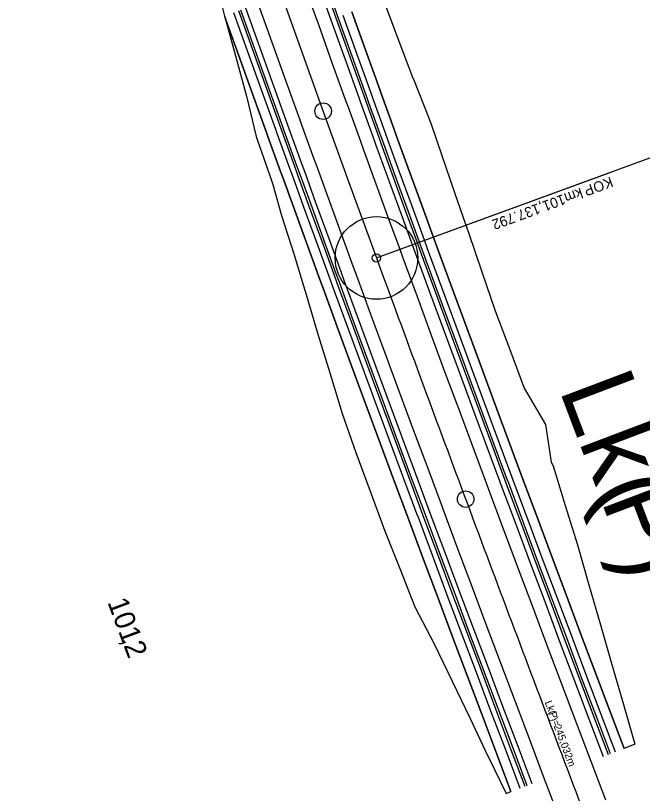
# Model space of a CAD drawing. Extents: x -678487 to -674601, y -1104811 to -1093295.
# Drawn here: x -677039.7 to -676888, y -1098001.8 to -1097813.6 of the extents above; entities that cross this region are included whole.
import ezdxf

# ---------------------------------------------------------------- set-up
doc = ezdxf.new("R2010")
doc.units = 0
for name, color, linetype in [('SOxxxxxx_Koleje_hlavní_body_Popis', 7, 'Continuous'), ('SOxxxxxx_Koleje_hlavní_body_Popis10', 7, 'Continuous'), ('SOxxxxxx_Koleje_param další_Popis', 7, 'Continuous'), ('SOxxxxxx_Koleje_param další_Popis10', 7, 'Continuous'), ('SOxxxxxx_Osa_bod_P', 7, 'Continuous'), ('SOxxxxxx_Staničení_Popis', 7, 'Continuous'), ('SOxxxxxx_ŽSp_hrana', 7, 'Continuous'), ('SOxxxxxx_ŽSp_odvodnění', 7, 'Continuous'), ('SOxxxxxx_ŽSp_zářez_hrana', 7, 'Continuous'), ('SOxxxxxx_ŽSp_zářez_plocha', 7, 'Continuous')]:
    doc.layers.add(name, color=color, linetype=linetype)

msp = doc.modelspace()

# ---------------------------------------------------------------- linework, layer by layer
at = {"layer": 'SOxxxxxx_Koleje_hlavní_body_Popis'}
for q in [(-676896.01, -1097851.63), (-676952.35, -1097872.26)]:
    msp.add_line((-676952.35, -1097872.26), q, dxfattribs=at)
msp.add_circle((-676952.35, -1097872.26), 1, dxfattribs=at)
at = {"layer": 'SOxxxxxx_Koleje_hlavní_body_Popis10'}
for q in [(-676388.94, -1097665.94), (-676952.35, -1097872.26)]:
    msp.add_line((-676952.35, -1097872.26), q, dxfattribs=at)
msp.add_circle((-676952.35, -1097872.26), 10, dxfattribs=at)
at = {"layer": 'SOxxxxxx_Osa_bod_P'}
msp.add_arc((-668968.6, -1094948.57), 8502.25, 183.991255, 200.113006, dxfattribs=at)
msp.add_open_spline([(-676952.35, -1097872.26), (-676945.32, -1097891.44), (-676931.16, -1097929.74), (-676909.55, -1097987.06), (-676887.79, -1098044.32), (-676873.18, -1098082.46), (-676865.88, -1098101.53)], degree=3, dxfattribs=at)
at = {"layer": 'SOxxxxxx_Staničení_Popis'}
for p, q in [((-676965.26, -1097836.75), (-676965.26, -1097836.75)), ((-676930.76, -1097930.61), (-676930.76, -1097930.61))]:
    msp.add_line(p, q, dxfattribs=at)
for centre in [(-676965.26, -1097836.75), (-676930.76, -1097930.61)]:
    msp.add_circle(centre, 2, dxfattribs=at)
at = {"layer": 'SOxxxxxx_ŽSp_hrana'}
for p, q in [((-676969.79, -1097806.37), (-676966.42, -1097815.78)), ((-676981.03, -1097810.64), (-676977.66, -1097820.05)), ((-676966.42, -1097815.78), (-676963.04, -1097825.19)), ((-676977.66, -1097820.05), (-676974.27, -1097829.47)), ((-676963.04, -1097825.19), (-676959.65, -1097834.6)), ((-676974.27, -1097829.47), (-676970.88, -1097838.88)), ((-676959.65, -1097834.6), (-676959.31, -1097835.54)), ((-676959.31, -1097835.54), (-676956.25, -1097844.01)), ((-676970.88, -1097838.88), (-676970.54, -1097839.81)), ((-676970.54, -1097839.81), (-676967.48, -1097848.28)), ((-676956.25, -1097844.01), (-676955.48, -1097846.12)), ((-676955.48, -1097846.12), (-676952.83, -1097853.41)), ((-676967.48, -1097848.28), (-676966.71, -1097850.39)), ((-676966.71, -1097850.39), (-676964.07, -1097857.68)), ((-676952.83, -1097853.41), (-676949.41, -1097862.8)), ((-676964.07, -1097857.68), (-676960.64, -1097867.08)), ((-676949.41, -1097862.8), (-676946.73, -1097870.13)), ((-676960.64, -1097867.08), (-676957.96, -1097874.4)), ((-676946.73, -1097870.13), (-676945.97, -1097872.2)), ((-676945.97, -1097872.2), (-676942.52, -1097881.58)), ((-676957.96, -1097874.4), (-676957.21, -1097876.47)), ((-676957.21, -1097876.47), (-676953.76, -1097885.86)), ((-676942.52, -1097881.58), (-676939.07, -1097890.97)), ((-676953.76, -1097885.86), (-676950.3, -1097895.24)), ((-676939.07, -1097890.97), (-676935.6, -1097900.35)), ((-676950.3, -1097895.24), (-676946.83, -1097904.62)), ((-676935.6, -1097900.35), (-676932.12, -1097909.72)), ((-676946.83, -1097904.62), (-676943.36, -1097914)), ((-676932.12, -1097909.72), (-676928.64, -1097919.1)), ((-676943.36, -1097914), (-676939.87, -1097923.37)), ((-676928.64, -1097919.1), (-676925.47, -1097927.58)), ((-676939.87, -1097923.37), (-676936.71, -1097931.85)), ((-676925.47, -1097927.58), (-676925.14, -1097928.47)), ((-676925.14, -1097928.47), (-676921.64, -1097937.83)), ((-676936.71, -1097931.85), (-676936.38, -1097932.74)), ((-676936.38, -1097932.74), (-676932.87, -1097942.11)), ((-676921.64, -1097937.83), (-676918.13, -1097947.2)), ((-676932.87, -1097942.11), (-676929.36, -1097951.47)), ((-676918.13, -1097947.2), (-676914.61, -1097956.56)), ((-676929.36, -1097951.47), (-676925.85, -1097960.83)), ((-676914.61, -1097956.56), (-676911.09, -1097965.92)), ((-676925.85, -1097960.83), (-676922.32, -1097970.19)), ((-676911.09, -1097965.92), (-676907.56, -1097975.27)), ((-676922.32, -1097970.19), (-676918.79, -1097979.55)), ((-676907.56, -1097975.27), (-676903.91, -1097984.91)), ((-676918.79, -1097979.55), (-676915.14, -1097989.19)), ((-676903.91, -1097984.91), (-676900.48, -1097993.98)), ((-676915.14, -1097989.19), (-676911.71, -1097998.25)), ((-676900.48, -1097993.98), (-676896.93, -1098003.33)), ((-676911.71, -1097998.25), (-676908.16, -1098007.6))]:
    msp.add_line(p, q, dxfattribs=at)
at = {"layer": 'SOxxxxxx_ŽSp_odvodnění'}
for p, q in [((-676965.58, -1097804.77), (-676962.22, -1097814.18)), ((-676965.07, -1097804.57), (-676961.7, -1097813.99)), ((-676985.75, -1097812.43), (-676982.38, -1097821.85)), ((-676985.23, -1097812.24), (-676981.86, -1097821.65)), ((-676962.22, -1097814.18), (-676958.83, -1097823.59)), ((-676961.7, -1097813.99), (-676958.32, -1097823.4)), ((-676982.38, -1097821.85), (-676978.99, -1097831.26)), ((-676981.86, -1097821.65), (-676978.48, -1097831.07)), ((-676958.83, -1097823.59), (-676955.44, -1097833)), ((-676958.32, -1097823.4), (-676954.93, -1097832.81)), ((-676978.99, -1097831.26), (-676975.6, -1097840.67)), ((-676978.48, -1097831.07), (-676975.09, -1097840.48)), ((-676955.44, -1097833), (-676955.1, -1097833.94)), ((-676955.1, -1097833.94), (-676952.04, -1097842.41)), ((-676954.93, -1097832.81), (-676954.59, -1097833.74)), ((-676954.59, -1097833.74), (-676951.53, -1097842.21)), ((-676975.6, -1097840.67), (-676975.26, -1097841.61)), ((-676975.26, -1097841.61), (-676972.2, -1097850.08)), ((-676975.09, -1097840.48), (-676974.75, -1097841.41)), ((-676974.75, -1097841.41), (-676971.69, -1097849.88)), ((-676952.04, -1097842.41), (-676951.27, -1097844.52)), ((-676951.53, -1097842.21), (-676950.76, -1097844.32)), ((-676951.27, -1097844.52), (-676948.63, -1097851.81)), ((-676950.76, -1097844.32), (-676948.11, -1097851.61)), ((-676972.2, -1097850.08), (-676971.43, -1097852.19)), ((-676971.69, -1097849.88), (-676970.92, -1097851.99)), ((-676971.43, -1097852.19), (-676968.79, -1097859.48)), ((-676970.92, -1097851.99), (-676968.27, -1097859.28)), ((-676948.63, -1097851.81), (-676945.2, -1097861.2)), ((-676948.11, -1097851.61), (-676944.69, -1097861.01)), ((-676968.79, -1097859.48), (-676965.36, -1097868.87)), ((-676968.27, -1097859.28), (-676964.85, -1097868.68)), ((-676945.2, -1097861.2), (-676942.52, -1097868.53)), ((-676944.69, -1097861.01), (-676942.01, -1097868.33)), ((-676965.36, -1097868.87), (-676962.68, -1097876.2)), ((-676964.85, -1097868.68), (-676962.17, -1097876)), ((-676942.52, -1097868.53), (-676941.77, -1097870.59)), ((-676942.01, -1097868.33), (-676941.25, -1097870.4)), ((-676941.77, -1097870.59), (-676938.32, -1097879.98)), ((-676941.25, -1097870.4), (-676937.8, -1097879.79)), ((-676962.68, -1097876.2), (-676961.92, -1097878.27)), ((-676962.17, -1097876), (-676961.41, -1097878.07)), ((-676961.92, -1097878.27), (-676958.48, -1097887.65)), ((-676961.41, -1097878.07), (-676957.96, -1097887.46)), ((-676938.32, -1097879.98), (-676934.86, -1097889.37)), ((-676937.8, -1097879.79), (-676934.35, -1097889.17)), ((-676958.48, -1097887.65), (-676955.02, -1097897.04)), ((-676957.96, -1097887.46), (-676954.51, -1097896.84)), ((-676934.86, -1097889.37), (-676931.39, -1097898.75)), ((-676934.35, -1097889.17), (-676930.88, -1097898.55)), ((-676955.02, -1097897.04), (-676951.55, -1097906.42)), ((-676954.51, -1097896.84), (-676951.04, -1097906.22)), ((-676931.39, -1097898.75), (-676927.92, -1097908.12)), ((-676930.88, -1097898.55), (-676927.4, -1097907.93)), ((-676951.55, -1097906.42), (-676948.08, -1097915.79)), ((-676951.04, -1097906.22), (-676947.56, -1097915.6)), ((-676927.92, -1097908.12), (-676924.43, -1097917.5)), ((-676927.4, -1097907.93), (-676923.92, -1097917.3)), ((-676948.08, -1097915.79), (-676944.59, -1097925.17)), ((-676947.56, -1097915.6), (-676944.08, -1097924.97)), ((-676924.43, -1097917.5), (-676921.27, -1097925.98)), ((-676923.92, -1097917.3), (-676920.75, -1097925.78)), ((-676944.59, -1097925.17), (-676941.43, -1097933.65)), ((-676944.08, -1097924.97), (-676940.91, -1097933.45)), ((-676921.27, -1097925.98), (-676920.94, -1097926.87)), ((-676920.75, -1097925.78), (-676920.42, -1097926.67)), ((-676920.94, -1097926.87), (-676917.43, -1097936.23)), ((-676920.42, -1097926.67), (-676916.92, -1097936.04)), ((-676941.43, -1097933.65), (-676941.1, -1097934.54)), ((-676940.91, -1097933.45), (-676940.58, -1097934.34)), ((-676941.1, -1097934.54), (-676937.59, -1097943.9)), ((-676940.58, -1097934.34), (-676937.08, -1097943.71)), ((-676917.43, -1097936.23), (-676913.92, -1097945.6)), ((-676916.92, -1097936.04), (-676913.41, -1097945.4)), ((-676937.59, -1097943.9), (-676934.08, -1097953.27)), ((-676937.08, -1097943.71), (-676933.57, -1097953.07)), ((-676913.92, -1097945.6), (-676910.41, -1097954.96)), ((-676913.41, -1097945.4), (-676909.89, -1097954.76)), ((-676934.08, -1097953.27), (-676930.57, -1097962.63)), ((-676933.57, -1097953.07), (-676930.05, -1097962.43)), ((-676910.41, -1097954.96), (-676906.88, -1097964.32)), ((-676909.89, -1097954.76), (-676906.37, -1097964.12)), ((-676930.57, -1097962.63), (-676927.04, -1097971.99)), ((-676930.05, -1097962.43), (-676926.53, -1097971.79)), ((-676906.88, -1097964.32), (-676903.35, -1097973.67)), ((-676906.37, -1097964.12), (-676902.84, -1097973.48)), ((-676927.04, -1097971.99), (-676923.51, -1097981.34)), ((-676926.53, -1097971.79), (-676923, -1097981.15)), ((-676902.84, -1097973.48), (-676899.19, -1097983.12)), ((-676903.35, -1097973.67), (-676899.7, -1097983.31)), ((-676923.51, -1097981.34), (-676919.86, -1097990.99)), ((-676923, -1097981.15), (-676919.35, -1097990.79)), ((-676899.7, -1097983.31), (-676896.27, -1097992.38)), ((-676899.19, -1097983.12), (-676895.76, -1097992.18)), ((-676919.86, -1097990.99), (-676916.43, -1098000.05)), ((-676919.35, -1097990.79), (-676915.92, -1097999.85))]:
    msp.add_line(p, q, dxfattribs=at)
at = {"layer": 'SOxxxxxx_ŽSp_zářez_hrana'}
for p, q in [((-676966.78, -1097805.22), (-676963.41, -1097814.64)), ((-676990.51, -1097808.03), (-676989.16, -1097813.73)), ((-676950.65, -1097809.78), (-676947.18, -1097819.16)), ((-676986.94, -1097812.89), (-676983.57, -1097822.3)), ((-676984.04, -1097811.78), (-676980.67, -1097821.2)), ((-676960.5, -1097813.53), (-676957.12, -1097822.94)), ((-676958.34, -1097812.71), (-676954.96, -1097822.12)), ((-676989.16, -1097813.73), (-676985.74, -1097823.13)), ((-676989.12, -1097813.71), (-676986.46, -1097823.4)), ((-676963.41, -1097814.64), (-676960.03, -1097824.05)), ((-676947.18, -1097819.16), (-676943.61, -1097828.5)), ((-676983.57, -1097822.3), (-676980.19, -1097831.72)), ((-676980.67, -1097821.2), (-676977.28, -1097830.61)), ((-676957.12, -1097822.94), (-676953.73, -1097832.35)), ((-676954.96, -1097822.12), (-676951.56, -1097831.53)), ((-676986.46, -1097823.4), (-676983.83, -1097833.1)), ((-676985.74, -1097823.13), (-676982.36, -1097832.54)), ((-676960.03, -1097824.05), (-676956.64, -1097833.46)), ((-676943.61, -1097828.5), (-676943.24, -1097829.42)), ((-676943.24, -1097829.42), (-676939.88, -1097837.78)), ((-676980.19, -1097831.72), (-676976.8, -1097841.13)), ((-676977.28, -1097830.61), (-676973.89, -1097840.02)), ((-676953.73, -1097832.35), (-676953.39, -1097833.29)), ((-676951.56, -1097831.53), (-676951.23, -1097832.46)), ((-676983.83, -1097833.1), (-676981.51, -1097842.92)), ((-676982.36, -1097832.54), (-676978.97, -1097841.95)), ((-676956.64, -1097833.46), (-676956.3, -1097834.39)), ((-676953.39, -1097833.29), (-676950.33, -1097841.76)), ((-676951.23, -1097832.46), (-676948.16, -1097840.93)), ((-676956.3, -1097834.39), (-676953.24, -1097842.86)), ((-676939.88, -1097837.78), (-676939.1, -1097839.88)), ((-676976.8, -1097841.13), (-676976.46, -1097842.06)), ((-676973.89, -1097840.02), (-676973.55, -1097840.96)), ((-676973.55, -1097840.96), (-676970.49, -1097849.43)), ((-676950.33, -1097841.76), (-676949.56, -1097843.87)), ((-676948.16, -1097840.93), (-676947.4, -1097843.04)), ((-676939.1, -1097839.88), (-676936.61, -1097847.24)), ((-676981.51, -1097842.92), (-676981.14, -1097843.84)), ((-676978.97, -1097841.95), (-676978.63, -1097842.89)), ((-676978.63, -1097842.89), (-676975.56, -1097851.36)), ((-676976.46, -1097842.06), (-676973.4, -1097850.53)), ((-676953.24, -1097842.86), (-676952.47, -1097844.97)), ((-676947.4, -1097843.04), (-676944.75, -1097850.33)), ((-676981.14, -1097843.84), (-676978.16, -1097852.35)), ((-676952.47, -1097844.97), (-676949.82, -1097852.26)), ((-676949.56, -1097843.87), (-676946.92, -1097851.16)), ((-676936.61, -1097847.24), (-676933.4, -1097856.71)), ((-676973.4, -1097850.53), (-676972.63, -1097852.65)), ((-676970.49, -1097849.43), (-676969.72, -1097851.54)), ((-676946.92, -1097851.16), (-676943.49, -1097860.55)), ((-676944.75, -1097850.33), (-676941.32, -1097859.73)), ((-676978.16, -1097852.35), (-676977.43, -1097854.47)), ((-676975.56, -1097851.36), (-676974.8, -1097853.47)), ((-676972.63, -1097852.65), (-676969.98, -1097859.93)), ((-676969.72, -1097851.54), (-676967.08, -1097858.83)), ((-676949.82, -1097852.26), (-676946.4, -1097861.66)), ((-676977.43, -1097854.47), (-676975.31, -1097861.96)), ((-676974.8, -1097853.47), (-676972.15, -1097860.76)), ((-676933.4, -1097856.71), (-676930.78, -1097864.05)), ((-676969.98, -1097859.93), (-676966.56, -1097869.33)), ((-676967.08, -1097858.83), (-676963.65, -1097868.22)), ((-676943.49, -1097860.55), (-676940.81, -1097867.87)), ((-676941.32, -1097859.73), (-676938.64, -1097867.05)), ((-676975.31, -1097861.96), (-676972.27, -1097871.5)), ((-676972.15, -1097860.76), (-676968.73, -1097870.15)), ((-676946.4, -1097861.66), (-676943.72, -1097868.98)), ((-676930.78, -1097864.05), (-676930.06, -1097866.14)), ((-676930.06, -1097866.14), (-676926.81, -1097875.6)), ((-676940.81, -1097867.87), (-676940.05, -1097869.94)), ((-676938.64, -1097867.05), (-676937.89, -1097869.12)), ((-676966.56, -1097869.33), (-676963.88, -1097876.65)), ((-676963.65, -1097868.22), (-676960.97, -1097875.55)), ((-676943.72, -1097868.98), (-676942.96, -1097871.05)), ((-676940.05, -1097869.94), (-676936.61, -1097879.33)), ((-676937.89, -1097869.12), (-676934.44, -1097878.51)), ((-676972.27, -1097871.5), (-676970, -1097878.98)), ((-676968.73, -1097870.15), (-676966.05, -1097877.48)), ((-676942.96, -1097871.05), (-676939.51, -1097880.44)), ((-676960.97, -1097875.55), (-676960.21, -1097877.62)), ((-676926.81, -1097875.6), (-676923.58, -1097885.07)), ((-676966.05, -1097877.48), (-676965.29, -1097879.55)), ((-676963.88, -1097876.65), (-676963.12, -1097878.72)), ((-676970, -1097878.98), (-676969.37, -1097881.1)), ((-676963.12, -1097878.72), (-676959.67, -1097888.11)), ((-676960.21, -1097877.62), (-676956.77, -1097887)), ((-676936.61, -1097879.33), (-676933.15, -1097888.72)), ((-676934.44, -1097878.51), (-676930.98, -1097887.89)), ((-676969.37, -1097881.1), (-676966.56, -1097890.73)), ((-676965.29, -1097879.55), (-676961.84, -1097888.93)), ((-676939.51, -1097880.44), (-676936.06, -1097889.82)), ((-676923.58, -1097885.07), (-676920.08, -1097894.44)), ((-676959.67, -1097888.11), (-676956.22, -1097897.49)), ((-676956.77, -1097887), (-676953.31, -1097896.39)), ((-676933.15, -1097888.72), (-676929.68, -1097898.1)), ((-676930.98, -1097887.89), (-676927.52, -1097897.27)), ((-676961.84, -1097888.93), (-676958.39, -1097898.32)), ((-676936.06, -1097889.82), (-676932.59, -1097899.2)), ((-676966.56, -1097890.73), (-676963.59, -1097900.3)), ((-676920.08, -1097894.44), (-676916.56, -1097903.8)), ((-676956.22, -1097897.49), (-676952.75, -1097906.87)), ((-676953.31, -1097896.39), (-676949.84, -1097905.77)), ((-676929.68, -1097898.1), (-676926.21, -1097907.47)), ((-676927.52, -1097897.27), (-676924.04, -1097906.65)), ((-676958.39, -1097898.32), (-676954.92, -1097907.7)), ((-676932.59, -1097899.2), (-676929.11, -1097908.58)), ((-676963.59, -1097900.3), (-676960.62, -1097909.87)), ((-676916.56, -1097903.8), (-676911.43, -1097912.55)), ((-676952.75, -1097906.87), (-676949.27, -1097916.25)), ((-676949.84, -1097905.77), (-676946.37, -1097915.14)), ((-676926.21, -1097907.47), (-676922.72, -1097916.85)), ((-676924.04, -1097906.65), (-676920.55, -1097916.02)), ((-676954.92, -1097907.7), (-676951.44, -1097917.08)), ((-676929.11, -1097908.58), (-676925.63, -1097917.95)), ((-676960.62, -1097909.87), (-676957.33, -1097919.31)), ((-676911.43, -1097912.55), (-676910.03, -1097921.7)), ((-676946.37, -1097915.14), (-676942.88, -1097924.52)), ((-676949.27, -1097916.25), (-676945.79, -1097925.62)), ((-676922.72, -1097916.85), (-676919.56, -1097925.33)), ((-676920.55, -1097916.02), (-676917.39, -1097924.5)), ((-676951.44, -1097917.08), (-676947.96, -1097926.45)), ((-676925.63, -1097917.95), (-676922.46, -1097926.43)), ((-676957.33, -1097919.31), (-676953.87, -1097928.7)), ((-676910.03, -1097921.7), (-676909.53, -1097922.53)), ((-676909.53, -1097922.53), (-676906.66, -1097932.13)), ((-676942.88, -1097924.52), (-676939.72, -1097933)), ((-676917.39, -1097924.5), (-676917.06, -1097925.39)), ((-676945.79, -1097925.62), (-676942.62, -1097934.1)), ((-676922.46, -1097926.43), (-676922.13, -1097927.32)), ((-676919.56, -1097925.33), (-676919.23, -1097926.22)), ((-676919.23, -1097926.22), (-676915.72, -1097935.58)), ((-676917.06, -1097925.39), (-676913.56, -1097934.76)), ((-676947.96, -1097926.45), (-676944.79, -1097934.93)), ((-676922.13, -1097927.32), (-676918.63, -1097936.69)), ((-676953.87, -1097928.7), (-676950.74, -1097937.19)), ((-676939.72, -1097933), (-676939.39, -1097933.89)), ((-676939.39, -1097933.89), (-676935.88, -1097943.25)), ((-676906.66, -1097932.13), (-676903.64, -1097941.68)), ((-676944.79, -1097934.93), (-676944.46, -1097935.82)), ((-676944.46, -1097935.82), (-676940.96, -1097945.18)), ((-676942.62, -1097934.1), (-676942.29, -1097934.99)), ((-676942.29, -1097934.99), (-676938.79, -1097944.36)), ((-676915.72, -1097935.58), (-676912.21, -1097944.95)), ((-676913.56, -1097934.76), (-676910.04, -1097944.12)), ((-676950.74, -1097937.19), (-676950.41, -1097938.08)), ((-676918.63, -1097936.69), (-676915.12, -1097946.05)), ((-676950.41, -1097938.08), (-676946.69, -1097947.37)), ((-676935.88, -1097943.25), (-676932.37, -1097952.62)), ((-676903.64, -1097941.68), (-676900.9, -1097951.34)), ((-676940.96, -1097945.18), (-676937.45, -1097954.55)), ((-676938.79, -1097944.36), (-676935.28, -1097953.72)), ((-676912.21, -1097944.95), (-676908.7, -1097954.31)), ((-676910.04, -1097944.12), (-676906.53, -1097953.48)), ((-676915.12, -1097946.05), (-676911.6, -1097955.41)), ((-676946.69, -1097947.37), (-676943.02, -1097956.67)), ((-676932.37, -1097952.62), (-676928.86, -1097961.98)), ((-676900.9, -1097951.34), (-676898.13, -1097960.99)), ((-676937.45, -1097954.55), (-676933.93, -1097963.91)), ((-676935.28, -1097953.72), (-676931.76, -1097963.08)), ((-676908.7, -1097954.31), (-676905.17, -1097963.66)), ((-676906.53, -1097953.48), (-676903, -1097962.84)), ((-676911.6, -1097955.41), (-676908.08, -1097964.77)), ((-676943.02, -1097956.67), (-676938.35, -1097965.59)), ((-676928.86, -1097961.98), (-676925.33, -1097971.34)), ((-676898.13, -1097960.99), (-676895.36, -1097970.63)), ((-676933.93, -1097963.91), (-676930.41, -1097973.27)), ((-676931.76, -1097963.08), (-676928.24, -1097972.44)), ((-676905.17, -1097963.66), (-676901.64, -1097973.02)), ((-676903, -1097962.84), (-676899.47, -1097972.2)), ((-676938.35, -1097965.59), (-676934.04, -1097974.65)), ((-676908.08, -1097964.77), (-676904.55, -1097974.13)), ((-676925.33, -1097971.34), (-676921.8, -1097980.69)), ((-676895.36, -1097970.63), (-676892.58, -1097980.27)), ((-676930.41, -1097973.27), (-676926.87, -1097982.62)), ((-676928.24, -1097972.44), (-676924.71, -1097981.8)), ((-676901.64, -1097973.02), (-676897.99, -1097982.66)), ((-676899.47, -1097972.2), (-676895.82, -1097981.84)), ((-676934.04, -1097974.65), (-676929.67, -1097983.69)), ((-676904.55, -1097974.13), (-676900.9, -1097983.77)), ((-676921.8, -1097980.69), (-676918.15, -1097990.34)), ((-676892.58, -1097980.27), (-676889.82, -1097989.92)), ((-676926.87, -1097982.62), (-676923.23, -1097992.27)), ((-676924.71, -1097981.8), (-676921.06, -1097991.44)), ((-676897.99, -1097982.66), (-676894.56, -1097991.73)), ((-676895.82, -1097981.84), (-676892.39, -1097990.9)), ((-676929.67, -1097983.69), (-676925.39, -1097992.76)), ((-676900.9, -1097983.77), (-676897.47, -1097992.83)), ((-676918.15, -1097990.34), (-676914.72, -1097999.4)), ((-676923.23, -1097992.27), (-676919.79, -1098001.33)), ((-676921.06, -1097991.44), (-676917.63, -1098000.5)), ((-676925.39, -1097992.76), (-676925.26, -1097993.04)), ((-676925.26, -1097993.04), (-676920.97, -1098001.78))]:
    msp.add_line(p, q, dxfattribs=at)
at = {"layer": 'SOxxxxxx_ŽSp_zářez_plocha'}
for p, q in [((-676889.82, -1097989.92), (-676892.39, -1097990.9)), ((-676920.97, -1098001.78), (-676919.79, -1098001.33))]:
    msp.add_line(p, q, dxfattribs=at)
for points in [[(-676950.65, -1097809.78), (-676947.18, -1097819.16), (-676943.61, -1097828.5), (-676943.24, -1097829.42), (-676939.88, -1097837.78), (-676939.1, -1097839.88), (-676936.61, -1097847.24), (-676933.4, -1097856.71), (-676930.78, -1097864.05), (-676930.06, -1097866.14), (-676926.81, -1097875.6), (-676923.58, -1097885.07), (-676920.08, -1097894.44), (-676916.56, -1097903.8), (-676911.43, -1097912.55), (-676910.03, -1097921.7), (-676909.53, -1097922.53), (-676906.66, -1097932.13), (-676903.64, -1097941.68), (-676900.9, -1097951.34), (-676898.13, -1097960.99), (-676895.36, -1097970.63), (-676892.58, -1097980.27), (-676889.82, -1097989.92)], [(-676892.39, -1097990.9), (-676895.82, -1097981.84), (-676899.47, -1097972.2), (-676903, -1097962.84), (-676906.53, -1097953.48), (-676910.04, -1097944.12), (-676913.56, -1097934.76), (-676917.06, -1097925.39), (-676917.39, -1097924.5), (-676920.55, -1097916.02), (-676924.04, -1097906.65), (-676927.52, -1097897.27), (-676930.98, -1097887.89), (-676934.44, -1097878.51), (-676937.89, -1097869.12), (-676938.64, -1097867.05), (-676941.32, -1097859.73), (-676944.75, -1097850.33), (-676947.4, -1097843.04), (-676948.16, -1097840.93), (-676951.23, -1097832.46), (-676951.56, -1097831.53), (-676954.96, -1097822.12), (-676958.34, -1097812.71)], [(-676919.79, -1098001.33), (-676923.23, -1097992.27), (-676926.87, -1097982.62), (-676930.41, -1097973.27), (-676933.93, -1097963.91), (-676937.45, -1097954.55), (-676940.96, -1097945.18), (-676944.46, -1097935.82), (-676944.79, -1097934.93), (-676947.96, -1097926.45), (-676951.44, -1097917.08), (-676954.92, -1097907.7), (-676958.39, -1097898.32), (-676961.84, -1097888.93), (-676965.29, -1097879.55), (-676966.05, -1097877.48), (-676968.73, -1097870.15), (-676972.15, -1097860.76), (-676974.8, -1097853.47), (-676975.56, -1097851.36), (-676978.63, -1097842.89), (-676978.97, -1097841.95), (-676982.36, -1097832.54), (-676985.74, -1097823.13), (-676988.99, -1097814.19)], [(-676988.99, -1097814.19), (-676986.46, -1097823.4), (-676983.83, -1097833.1), (-676981.51, -1097842.92), (-676981.14, -1097843.84), (-676978.16, -1097852.35), (-676977.43, -1097854.47), (-676975.31, -1097861.96), (-676972.27, -1097871.5), (-676970, -1097878.98), (-676969.37, -1097881.1), (-676966.56, -1097890.73), (-676963.59, -1097900.3), (-676960.62, -1097909.87), (-676957.33, -1097919.31), (-676953.87, -1097928.7), (-676950.74, -1097937.19), (-676950.41, -1097938.08), (-676946.69, -1097947.37), (-676943.02, -1097956.67), (-676938.35, -1097965.59), (-676934.04, -1097974.65), (-676929.67, -1097983.69), (-676925.39, -1097992.76), (-676925.26, -1097993.04), (-676920.97, -1098001.78)]]:
    msp.add_lwpolyline(points, dxfattribs=at)

# ---------------------------------------------------------------- texts
at = {"layer": 'SOxxxxxx_Koleje_hlavní_body_Popis'}
for s, p in [('KO', (-676895.66, -1097852.57)), ('P', (-676900.29, -1097854.27)), (' km ', (-676902.09, -1097854.92)), ('101,137.792', (-676907.17, -1097856.78))]:
    msp.add_text(s, height=2.5, rotation=200.113, dxfattribs=at).set_placement(p)
at = {"layer": 'SOxxxxxx_Koleje_param další_Popis'}
for s, p in [('Lk(', (-676911.65, -1097979.75)), ('P', (-676910.64, -1097982.42)), (')=', (-676910.15, -1097983.71)), ('245,032m', (-676909.48, -1097985.48))]:
    msp.add_text(s, height=1.8, rotation=290.7322, dxfattribs=at).set_placement(p)
at = {"layer": 'SOxxxxxx_Koleje_param další_Popis10'}
for s, p in [('Lk(', (-676908.22, -1097903.97)), ('P', (-676898.08, -1097930.77)), (')=', (-676893.21, -1097943.62))]:
    msp.add_text(s, height=18, rotation=290.7322, dxfattribs=at).set_placement(p)
at = {"layer": 'SOxxxxxx_Staničení_Popis'}
for s, p in [('101', (-677017.53, -1097955.52)), (',', (-677014.18, -1097964.47)), ('2', (-677013.62, -1097965.97))]:
    msp.add_text(s, height=5, rotation=290.479, dxfattribs=at).set_placement(p)

doc.saveas('drawing.dxf')
